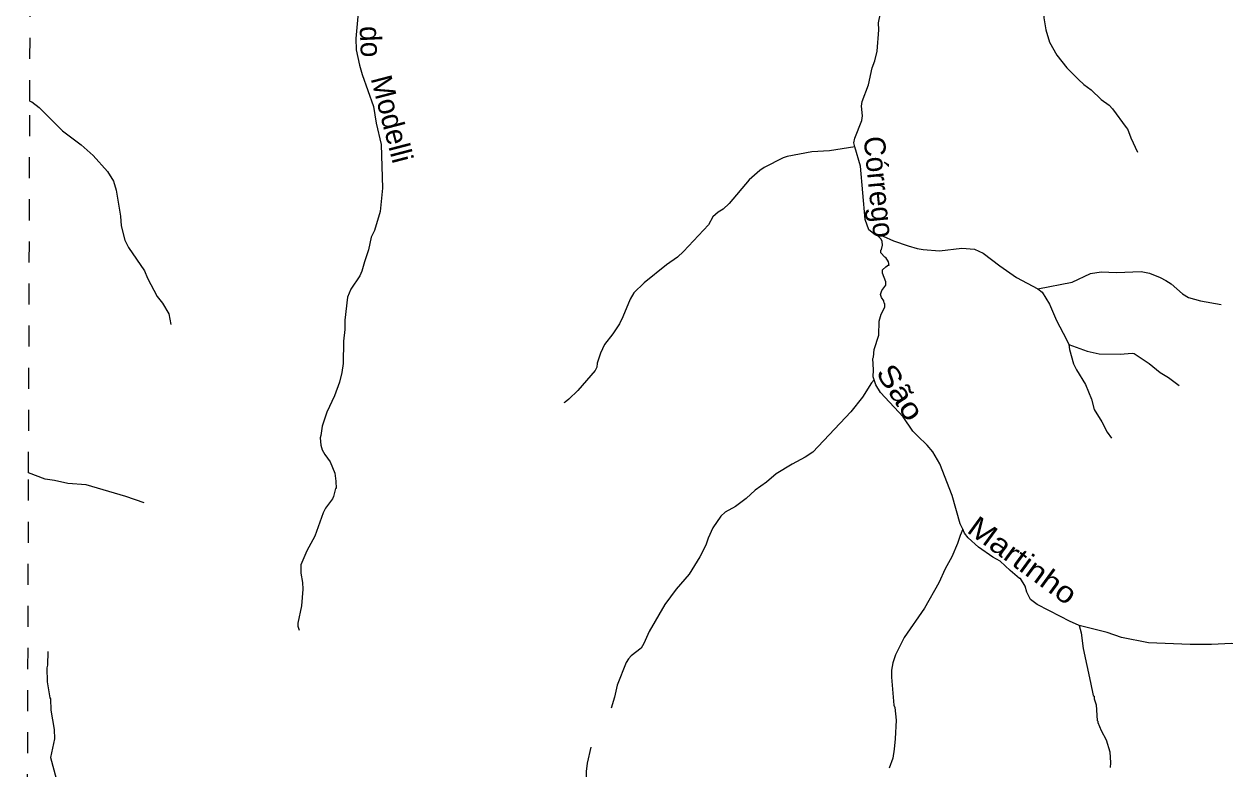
# Model space of a CAD drawing. Extents: x 551.6 to 577.6, y 7567 to 7594.7.
# Drawn here: x 551.61 to 557.32, y 7572.36 to 7575.9 of the extents above; entities that cross this region are included whole.
import ezdxf
from ezdxf.enums import TextEntityAlignment as Align

# ---------------------------------------------------------------- set-up
doc = ezdxf.new("R2010")
doc.units = 0
doc.header["$LTSCALE"] = 0.04
doc.linetypes.add('SHORT_DASHED', pattern=[2.7, 1.5, -1.2])
doc.layers.add('53', color=7, linetype='SHORT_DASHED', lineweight=13)
doc.layers.add('7', color=7, linetype='Continuous', lineweight=25)
doc.layers.add('61', color=7, linetype='Continuous')

msp = doc.modelspace()

# ---------------------------------------------------------------- linework, layer by layer
at = {"layer": '53'}
msp.add_lwpolyline([(551.613, 7567.0572), (551.6165, 7568.1281), (551.6253, 7570.846), (551.6259, 7571.0339), (551.6348, 7573.7652), (551.6406, 7575.5319), (551.6443, 7576.6663), (551.6448, 7576.8423), (551.646, 7577.1998), (551.6475, 7577.6707), (551.6503, 7578.541), (551.6589, 7581.176)], dxfattribs=at)
at = {"layer": '7'}
for points in [[(555.895, 7576.4216), (555.9416, 7576.3709), (555.969, 7576.3492), (556.0125, 7576.325), (556.0447, 7576.3154), (556.0785, 7576.3122), (556.1461, 7576.3138), (556.1847, 7576.3073), (556.2547, 7576.2832), (556.2748, 7576.2735), (556.3239, 7576.2269), (556.3505, 7576.1882), (556.3939, 7576.111), (556.4269, 7576.0723), (556.4422, 7576.0482), (556.4583, 7575.9758), (556.4583, 7575.9275), (556.468, 7575.8695), (556.4865, 7575.8116), (556.5203, 7575.7504)], [(553.194, 7575.979), (553.1989, 7575.9339), (553.1892, 7575.8293), (553.1915, 7575.7752), (553.2069, 7575.7021), (553.2198, 7575.6587), (553.2745, 7575.5058), (553.2858, 7575.4269), (553.3099, 7575.3255), (553.3164, 7575.1179), (553.3051, 7575.0068), (553.2786, 7574.9174)], [(555.6567, 7575.7231), (555.6664, 7575.7681), (555.6744, 7575.8695), (555.6728, 7575.9033), (555.6826, 7575.9495)], [(556.5203, 7575.7504), (556.5678, 7575.69), (556.6233, 7575.6345), (556.6483, 7575.6112), (556.6837, 7575.5846), (556.7312, 7575.5387), (556.769, 7575.513), (556.7851, 7575.4953), (556.8494, 7575.406), (556.8527, 7575.4052), (556.8527, 7575.4011), (556.8559, 7575.4003), (556.872, 7575.3577), (556.9042, 7575.2893)], [(555.5606, 7575.3151), (555.5569, 7575.3335), (555.561, 7575.3561), (555.594, 7575.4398), (555.5972, 7575.4623), (555.5924, 7575.5074), (555.5964, 7575.5299), (555.6262, 7575.6088), (555.6439, 7575.6893), (555.6567, 7575.7231)], [(551.6406, 7575.5319), (551.6505, 7575.5275), (551.6843, 7575.5009), (551.7953, 7575.3907), (551.8854, 7575.3239), (551.9418, 7575.274), (552.0094, 7575.1967), (552.0384, 7575.1517), (552.0512, 7575.1082), (552.0722, 7574.9843), (552.0754, 7574.9392), (552.0915, 7574.8716), (552.1092, 7574.837), (552.1856, 7574.7251), (552.1993, 7574.6913), (552.2452, 7574.6028)], [(555.5606, 7575.3151), (555.4411, 7575.2949), (555.3558, 7575.2901), (555.2399, 7575.2691), (555.2206, 7575.2627), (555.1296, 7575.216), (555.1087, 7575.2015), (555.0588, 7575.1581), (554.9638, 7575.0446), (554.9357, 7575.0188), (554.9115, 7575.0036), (554.8865, 7574.9818), (554.8656, 7574.944), (554.7473, 7574.8168)], [(555.668, 7574.8925), (555.6568, 7574.8965), (555.6278, 7574.9199), (555.6101, 7574.9698), (555.5875, 7575.2225), (555.5606, 7575.3151)], [(553.2786, 7574.9174), (553.2633, 7574.886), (553.2496, 7574.8249), (553.2303, 7574.7686), (553.219, 7574.7235), (553.2093, 7574.701), (553.1667, 7574.6382), (553.1506, 7574.5996), (553.1369, 7574.4917), (553.1377, 7574.4466), (553.1313, 7574.3919), (553.1297, 7574.2857), (553.1232, 7574.2422), (553.112, 7574.1972), (553.0878, 7574.1312), (553.0516, 7574.0539), (553.0291, 7573.9879), (553.0234, 7573.9428)], [(555.7034, 7574.7903), (555.6841, 7574.8112), (555.6841, 7574.8241), (555.6873, 7574.8265), (555.6921, 7574.8474), (555.6905, 7574.8651), (555.6857, 7574.8764), (555.668, 7574.8925)], [(555.668, 7574.8925), (555.6951, 7574.8897), (555.7453, 7574.8683), (555.8145, 7574.8442), (555.8563, 7574.8313), (555.8853, 7574.8265), (555.9626, 7574.8201), (556.0688, 7574.8329), (556.13, 7574.8281), (556.1702, 7574.8096), (556.2499, 7574.7492), (556.3288, 7574.6945), (556.4301, 7574.6394)], [(554.7473, 7574.8168), (554.7184, 7574.7911), (554.6652, 7574.7533), (554.5606, 7574.668), (554.5115, 7574.6205), (554.493, 7574.5915), (554.4592, 7574.5062), (554.4423, 7574.474), (554.4117, 7574.4257), (554.3706, 7574.3758), (554.353, 7574.334), (554.3369, 7574.2873), (554.3353, 7574.268), (554.3272, 7574.2519), (554.2443, 7574.1569), (554.2024, 7574.1158), (554.184, 7574.1022), (554.1783, 7574.0982)], [(555.6526, 7574.2084), (555.6487, 7574.2213), (555.6503, 7574.2551), (555.6471, 7574.309), (555.6503, 7574.3147), (555.6527, 7574.3517), (555.6744, 7574.4193), (555.6761, 7574.4869), (555.6857, 7574.5191), (555.7034, 7574.5529), (555.7034, 7574.5682), (555.7002, 7574.5714), (555.6986, 7574.5826), (555.6881, 7574.598), (555.6825, 7574.6132), (555.6897, 7574.6318), (555.7082, 7574.6575), (555.7082, 7574.6728), (555.6921, 7574.7138), (555.6921, 7574.7299), (555.7074, 7574.7452), (555.7211, 7574.7532), (555.7235, 7574.7509), (555.7211, 7574.7685), (555.7083, 7574.7895), (555.7034, 7574.7903)], [(556.4301, 7574.6394), (556.5935, 7574.6712), (556.6805, 7574.7122), (556.732, 7574.7203), (556.8044, 7574.7179), (556.9219, 7574.7227), (556.9613, 7574.7138), (557.012, 7574.6945), (557.0394, 7574.68), (557.0643, 7574.6631), (557.1175, 7574.6156), (557.1456, 7574.5987), (557.2036, 7574.5826), (557.301, 7574.5658)], [(556.4301, 7574.6394), (556.4511, 7574.6237), (556.4857, 7574.5674), (556.5187, 7574.4901), (556.567, 7574.4), (556.578, 7574.3759)], [(552.2452, 7574.6028), (552.2709, 7574.5722), (552.3007, 7574.5207), (552.3104, 7574.47)], [(556.578, 7574.3759), (556.5806, 7574.3517), (556.6, 7574.2841), (556.6136, 7574.2551), (556.6563, 7574.1859), (556.6853, 7574.1151), (556.6981, 7574.0668), (556.7344, 7574.0088), (556.7597, 7573.9589), (556.7803, 7573.9308)], [(556.578, 7574.3759), (556.6644, 7574.3436), (556.7223, 7574.3307), (556.8221, 7574.3291), (556.8784, 7574.3348), (556.8881, 7574.3323), (556.9597, 7574.2849), (557.0112, 7574.243), (557.0507, 7574.2189), (557.1014, 7574.1803)], [(555.6526, 7574.2084), (555.6406, 7574.1939), (555.598, 7574.1247), (555.5417, 7574.0555), (555.3606, 7573.8639), (555.3252, 7573.8406), (555.2632, 7573.8076), (555.1867, 7573.7617), (555.1409, 7573.7215), (555.0877, 7573.6829), (555.0451, 7573.6442), (554.9936, 7573.6064), (554.9445, 7573.5783), (554.9236, 7573.5598), (554.8857, 7573.505), (554.864, 7573.4559), (554.8535, 7573.4229)], [(555.858, 7573.9412), (555.837, 7573.9638), (555.7903, 7574.0314), (555.6833, 7574.1481), (555.6599, 7574.1843), (555.6526, 7574.2084)], [(553.0234, 7573.9428), (553.021, 7573.9316), (553.0234, 7573.8978), (553.0299, 7573.8752), (553.0419, 7573.8535), (553.0685, 7573.8189), (553.0894, 7573.7642), (553.0951, 7573.7255), (553.0959, 7573.6917), (553.0934, 7573.6909), (553.0838, 7573.6531), (553.0782, 7573.6418), (553.046, 7573.5984), (553.0347, 7573.5759), (552.9945, 7573.4648), (552.9574, 7573.3956), (552.9285, 7573.3296), (552.9277, 7573.2893), (552.9357, 7573.2443), (552.9373, 7573.2137), (552.9317, 7573.134), (552.914, 7573.0511), (552.914, 7573.0382), (552.9212, 7573.0181)], [(556.0733, 7573.4983), (556.0607, 7573.5243), (556.0237, 7573.6579), (555.9642, 7573.8092), (555.9312, 7573.8656), (555.9038, 7573.897), (555.858, 7573.9412)], [(552.184, 7573.6233), (552.0963, 7573.6539), (551.908, 7573.7094), (551.8211, 7573.7151), (551.7583, 7573.7295), (551.714, 7573.736), (551.6348, 7573.7652)], [(556.0733, 7573.4983), (556.0607, 7573.468), (556.0495, 7573.4294), (556.0221, 7573.3666), (555.9907, 7573.3103), (555.9593, 7573.2427), (555.8917, 7573.1236), (555.796, 7572.9835), (555.7541, 7572.9014), (555.742, 7572.8628), (555.7356, 7572.829), (555.7356, 7572.7952), (555.7469, 7572.6616), (555.7509, 7572.6519), (555.7573, 7572.5908), (555.7533, 7572.5023), (555.7477, 7572.454)], [(556.5388, 7573.0833), (556.4278, 7573.1404), (556.3955, 7573.1646), (556.3778, 7573.1992), (556.3698, 7573.2282), (556.3481, 7573.2636), (556.3432, 7573.2644), (556.2982, 7573.3022), (556.2515, 7573.3465), (556.2169, 7573.3658), (556.1485, 7573.4125), (556.0994, 7573.4575), (556.0825, 7573.4793), (556.0733, 7573.4983)], [(554.8535, 7573.4229), (554.8246, 7573.3666), (554.7739, 7573.2845), (554.7119, 7573.2129), (554.658, 7573.1405), (554.5831, 7573.0125), (554.559, 7572.9545), (554.5453, 7572.9336), (554.4986, 7572.8958), (554.485, 7572.8821), (554.4737, 7572.8644), (554.4318, 7572.7566), (554.419, 7572.7002), (554.4029, 7572.6479)], [(556.6265, 7573.0412), (556.5807, 7573.0608), (556.5388, 7573.0833)], [(557.5859, 7572.9562), (557.4531, 7572.9497), (557.3919, 7572.9497), (557.3501, 7572.9553), (557.2551, 7572.9497), (557.1537, 7572.9497), (556.9557, 7572.9577), (556.8285, 7572.9835), (556.7593, 7573.0068), (556.6265, 7573.0412)], [(556.6265, 7573.0412), (556.6364, 7573.0063), (556.6466, 7572.932), (556.6804, 7572.7694), (556.6941, 7572.7083), (556.6981, 7572.7051), (556.6981, 7572.6922), (556.7078, 7572.6632), (556.7126, 7572.5891), (556.7159, 7572.5867), (556.7159, 7572.5803), (556.7319, 7572.5425), (556.7545, 7572.4974), (556.773, 7572.4411), (556.7762, 7572.388), (556.7738, 7572.3662)], [(551.7261, 7572.9167), (551.7245, 7572.8515), (551.7213, 7572.8403), (551.7229, 7572.7727), (551.7358, 7572.697), (551.739, 7572.693), (551.7406, 7572.6391), (551.7567, 7572.5473), (551.7583, 7572.5023), (551.739, 7572.4129), (551.7663, 7572.3139), (551.7704, 7572.2576), (551.7873, 7572.1449), (551.8017, 7572.087), (551.8082, 7572.0322), (551.809, 7571.9646)], [(554.3071, 7572.4628), (554.2894, 7572.3864), (554.2846, 7572.3477), (554.2837, 7572.2367), (554.2789, 7572.1916), (554.2789, 7572.0387), (554.2854, 7571.9244), (554.3154, 7571.7308)], [(555.7477, 7572.454), (555.742, 7572.4105), (555.7244, 7572.363)]]:
    msp.add_lwpolyline(points, dxfattribs=at)

# ---------------------------------------------------------------- texts
at = {"layer": '61'}
for s, rotation, p in [('do', 272.564, (553.211, 7575.8122)), ('Modelli', 284.59, (553.313, 7575.4344)), ('Córrego', 275.749, (555.6264, 7575.1194))]:
    msp.add_text(s, height=0.1, rotation=rotation, dxfattribs=at).set_placement(p, align=Align.CENTER)
for s, rotation, width, p in [('São', 302.81, 1.2, (555.7352, 7574.1216)), ('Martinho', 323.759, 1.15, (556.329, 7573.3098))]:
    msp.add_text(s, height=0.1, rotation=rotation, dxfattribs=dict(at, width=width)).set_placement(p, align=Align.CENTER)

doc.saveas('drawing.dxf')
